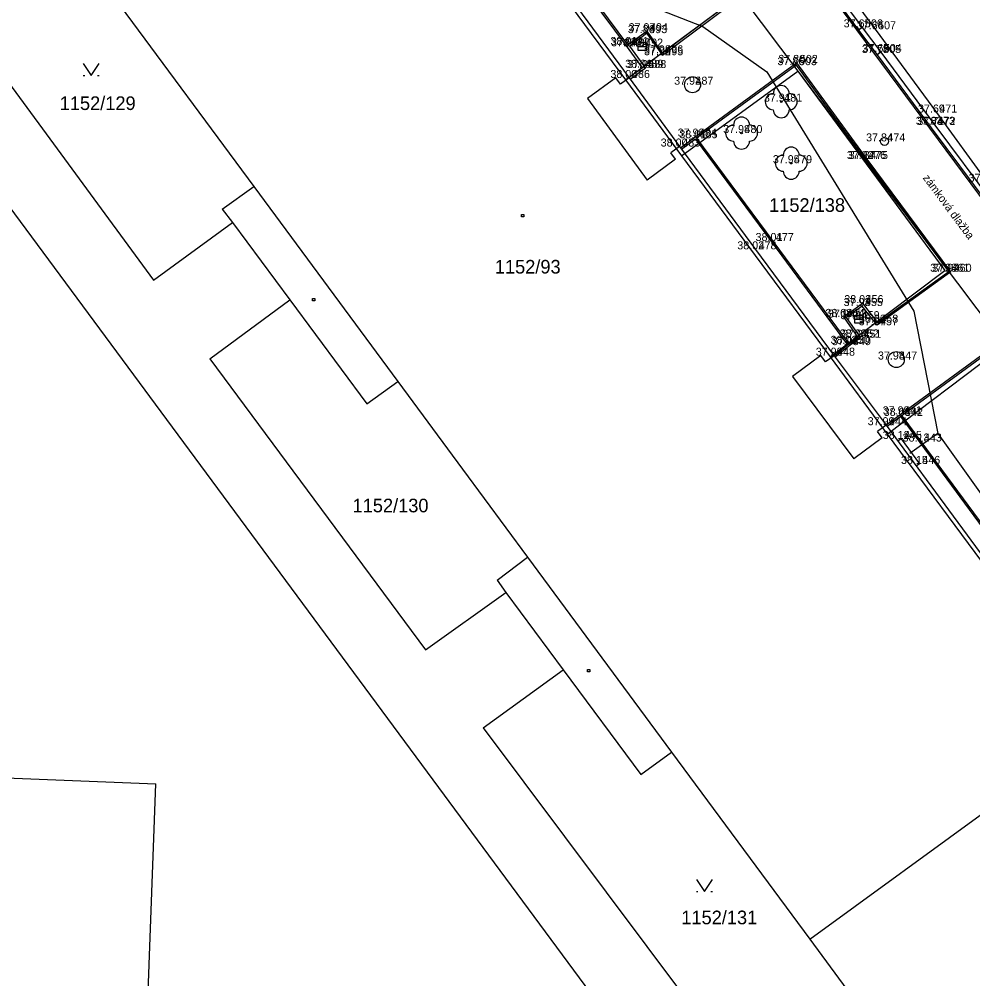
# Model space of a CAD drawing. Extents: x -609709 to -609357, y -1051535 to -1051131.
# Drawn here: x -609585.14 to -609555.38, y -1051361.09 to -1051331.13 of the extents above; entities that cross this region are included whole.
import ezdxf

# ---------------------------------------------------------------- set-up
doc = ezdxf.new("R2010")
doc.units = 0
for name, color, linetype in [('Vrstva 1', 7, 'Continuous'), ('Vrstva 10', 7, 'Continuous'), ('Vrstva 12', 7, 'Continuous'), ('Vrstva 2', 7, 'Continuous'), ('Vrstva 3', 7, 'Continuous'), ('Vrstva 4', 7, 'Continuous'), ('Vrstva 5', 7, 'Continuous'), ('Vrstva 7', 7, 'Continuous'), ('Vrstva 9', 7, 'Continuous')]:
    doc.layers.add(name, color=color, linetype=linetype)

msp = doc.modelspace()

# ---------------------------------------------------------------- linework, layer by layer
at = {"layer": 'Vrstva 1'}
for p, q in [((-609565.55, -1051331.51), (-609565.55, -1051331.51)), ((-609558.84, -1051331.39), (-609558.84, -1051331.39)), ((-609558.43, -1051331.45), (-609558.43, -1051331.45)), ((-609565.57, -1051331.57), (-609565.57, -1051331.57)), ((-609566.15, -1051331.94), (-609566.15, -1051331.94)), ((-609566.1, -1051331.98), (-609566.1, -1051331.98)), ((-609565.7, -1051331.99), (-609565.7, -1051331.99)), ((-609565.07, -1051332.2), (-609565.07, -1051332.2)), ((-609565.07, -1051332.26), (-609565.07, -1051332.26)), ((-609558.27, -1051332.19), (-609558.27, -1051332.19)), ((-609558.25, -1051332.16), (-609558.25, -1051332.16)), ((-609565.69, -1051332.65), (-609565.69, -1051332.65)), ((-609565.6, -1051332.66), (-609565.6, -1051332.66)), ((-609560.9, -1051332.57), (-609560.9, -1051332.57)), ((-609560.87, -1051332.5), (-609560.87, -1051332.5)), ((-609566.11, -1051332.97), (-609566.11, -1051332.97)), ((-609564.13, -1051333.18), (-609564.13, -1051333.18)), ((-609561.36, -1051333.71), (-609561.36, -1051333.71)), ((-609556.52, -1051334.05), (-609556.52, -1051334.05)), ((-609556.59, -1051334.43), (-609556.59, -1051334.43)), ((-609556.57, -1051334.44), (-609556.57, -1051334.44)), ((-609564.02, -1051334.8), (-609564.02, -1051334.8)), ((-609562.6, -1051334.69), (-609562.6, -1051334.69)), ((-609564.54, -1051335.11), (-609564.54, -1051335.11)), ((-609564, -1051334.85), (-609564, -1051334.85)), ((-609558.14, -1051334.95), (-609558.14, -1051334.95)), ((-609561.05, -1051335.63), (-609561.05, -1051335.63)), ((-609558.74, -1051335.5), (-609558.74, -1051335.5)), ((-609558.68, -1051335.5), (-609558.68, -1051335.5)), ((-609561.62, -1051338.06), (-609561.62, -1051338.06)), ((-609562.16, -1051338.32), (-609562.16, -1051338.32)), ((-609556.14, -1051339.02), (-609556.14, -1051339.02)), ((-609556.07, -1051339.02), (-609556.07, -1051339.02)), ((-609558.84, -1051340.09), (-609558.84, -1051340.09)), ((-609558.82, -1051340), (-609558.82, -1051340)), ((-609559.41, -1051340.43), (-609559.41, -1051340.43)), ((-609559.33, -1051340.45), (-609559.33, -1051340.45)), ((-609558.94, -1051340.5), (-609558.94, -1051340.5)), ((-609558.37, -1051340.69), (-609558.37, -1051340.69)), ((-609558.36, -1051340.61), (-609558.36, -1051340.61)), ((-609558.96, -1051341.07), (-609558.96, -1051341.07)), ((-609558.89, -1051341.08), (-609558.89, -1051341.08)), ((-609559.25, -1051341.27), (-609559.25, -1051341.27)), ((-609559.21, -1051341.31), (-609559.21, -1051341.31)), ((-609559.71, -1051341.64), (-609559.71, -1051341.64)), ((-609557.77, -1051341.76), (-609557.77, -1051341.76)), ((-609557.62, -1051343.47), (-609557.62, -1051343.47)), ((-609558.09, -1051343.81), (-609558.09, -1051343.81)), ((-609557.59, -1051343.52), (-609557.59, -1051343.52)), ((-609557.62, -1051344.24), (-609557.62, -1051344.24)), ((-609557, -1051344.32), (-609557, -1051344.32)), ((-609557.05, -1051345.02), (-609557.05, -1051345.02))]:
    msp.add_line(p, q, dxfattribs=at)
at = {"layer": 'Vrstva 10'}
for p, q in [((-609581.79, -1051300.71), (-609506.66, -1051402.14)), ((-609595.06, -1051324), (-609556.61, -1051376.01)), ((-609572.88, -1051324.02), (-609566.22, -1051333.03)), ((-609589.8, -1051327.23), (-609580.95, -1051339.28)), ((-609566.22, -1051333.03), (-609562.6, -1051330.34)), ((-609581.99, -1051330.72), (-609577.82, -1051336.36)), ((-609583.15, -1051332.515), (-609582.9, -1051332.89)), ((-609582.9, -1051332.89), (-609582.65, -1051332.515)), ((-609583.15, -1051332.89), (-609583.1, -1051332.89)), ((-609582.7, -1051332.89), (-609582.65, -1051332.89)), ((-609564.47, -1051335.4), (-609560.84, -1051332.76)), ((-609560.84, -1051332.76), (-609556.26, -1051338.98)), ((-609566.22, -1051333.03), (-609564.47, -1051335.4)), ((-609564.47, -1051335.4), (-609562.17, -1051338.51)), ((-609578.81, -1051337.07), (-609577.82, -1051336.36)), ((-609577.82, -1051336.36), (-609573.33, -1051342.45)), ((-609578.81, -1051337.07), (-609578.49, -1051337.48)), ((-609580.95, -1051339.28), (-609578.49, -1051337.48)), ((-609578.49, -1051337.48), (-609576.7, -1051339.9)), ((-609569.465, -1051337.235), (-609569.39, -1051337.235)), ((-609569.465, -1051337.31), (-609569.465, -1051337.235)), ((-609569.39, -1051337.31), (-609569.465, -1051337.31)), ((-609569.39, -1051337.235), (-609569.39, -1051337.31)), ((-609562.17, -1051338.51), (-609559.83, -1051341.68)), ((-609559.83, -1051341.68), (-609556.26, -1051338.98)), ((-609579.19, -1051341.74), (-609576.7, -1051339.9)), ((-609576.7, -1051339.9), (-609574.29, -1051343.14)), ((-609575.995, -1051339.855), (-609575.92, -1051339.855)), ((-609575.995, -1051339.93), (-609575.995, -1051339.855)), ((-609575.92, -1051339.855), (-609575.92, -1051339.93)), ((-609575.92, -1051339.93), (-609575.995, -1051339.93)), ((-609558.05, -1051344.09), (-609554.47, -1051341.38)), ((-609559.83, -1051341.68), (-609558.05, -1051344.09)), ((-609579.19, -1051341.74), (-609572.46, -1051350.82)), ((-609574.29, -1051343.14), (-609573.33, -1051342.45)), ((-609573.33, -1051342.45), (-609571.31, -1051345.18)), ((-609558.05, -1051344.09), (-609551.33, -1051353.19)), ((-609571.31, -1051345.18), (-609569.28, -1051347.93)), ((-609570.23, -1051348.65), (-609569.28, -1051347.93)), ((-609569.28, -1051347.93), (-609564.79, -1051354.02)), ((-609570.23, -1051348.65), (-609569.96, -1051349.03)), ((-609572.46, -1051350.82), (-609569.96, -1051349.03)), ((-609569.96, -1051349.03), (-609568.17, -1051351.45)), ((-609570.66, -1051353.26), (-609568.17, -1051351.45)), ((-609568.17, -1051351.45), (-609565.74, -1051354.72)), ((-609567.405, -1051351.435), (-609567.33, -1051351.435)), ((-609567.405, -1051351.51), (-609567.405, -1051351.435)), ((-609567.33, -1051351.51), (-609567.405, -1051351.51)), ((-609567.33, -1051351.435), (-609567.33, -1051351.51)), ((-609570.66, -1051353.26), (-609559.22, -1051368.54)), ((-609560.47, -1051359.86), (-609551.33, -1051353.19)), ((-609565.74, -1051354.72), (-609564.79, -1051354.02)), ((-609564.79, -1051354.02), (-609560.47, -1051359.86)), ((-609592.98, -1051354.53), (-609580.88, -1051355.01)), ((-609581.73, -1051378.07), (-609580.88, -1051355.01)), ((-609564.01, -1051357.995), (-609563.76, -1051358.37)), ((-609563.76, -1051358.37), (-609563.51, -1051357.995)), ((-609564.01, -1051358.37), (-609563.96, -1051358.37)), ((-609563.56, -1051358.37), (-609563.51, -1051358.37)), ((-609560.47, -1051359.86), (-609556.16, -1051365.7))]:
    msp.add_line(p, q, dxfattribs=at)
at = {"layer": 'Vrstva 12'}
for points in [[(-609615.546, -1051325.052), (-609614.108, -1051326.974), (-609589.099, -1051308.266), (-609582.815, -1051303.565), (-609514.844, -1051393.856), (-609499.807, -1051382.785), (-609467.693, -1051377.467)], [(-609567.26, -1051329.65), (-609566.61, -1051330.26), (-609563.81, -1051331.36), (-609561.81, -1051332.78), (-609557.22, -1051340.25), (-609556.47, -1051344.07), (-609557.345, -1051344.694)], [(-609556.47, -1051344.07), (-609551.22, -1051351.43), (-609546.41, -1051357.3), (-609545.59, -1051359.13), (-609546.284, -1051359.683)]]:
    msp.add_lwpolyline(points, dxfattribs=at)
at = {"layer": 'Vrstva 4'}
msp.add_line((-609566.19, -1051331.97), (-609569.24, -1051327.85), dxfattribs=at)
for points in [[(-609581.29, -1051300.49), (-609578.2, -1051304.72), (-609575.96, -1051307.74), (-609573.15, -1051311.54), (-609570.93, -1051314.56), (-609567.02, -1051319.88), (-609560.65, -1051328.46), (-609558.43, -1051331.45), (-609556.52, -1051334.05), (-609554.94, -1051336.21), (-609551.65, -1051340.58), (-609547.88, -1051345.71), (-609545.37, -1051349.12), (-609543.12, -1051352.14), (-609541.57, -1051354.24), (-609540.598, -1051355.492)], [(-609578.94, -1051314.61), (-609575.88, -1051312.34), (-609572.62, -1051316.75), (-609569.1, -1051321.53), (-609566.09, -1051325.58), (-609562.57, -1051330.32), (-609565.07, -1051332.2), (-609565.55, -1051331.51), (-609566.15, -1051331.94)], [(-609566.15, -1051331.94), (-609569.2, -1051327.82), (-609572.12, -1051323.85), (-609575.24, -1051319.63), (-609578.94, -1051314.61)], [(-609560.734, -1051329.062), (-609558.952, -1051331.474), (-609558.362, -1051332.244), (-609556.683, -1051334.523), (-609554.883, -1051336.942), (-609554.333, -1051337.712), (-609552.562, -1051340.114), (-609551.952, -1051340.904), (-609548.222, -1051345.943), (-609545.692, -1051349.353), (-609543.904, -1051351.772), (-609543.324, -1051352.602), (-609541.542, -1051355.005), (-609540.951, -1051355.766)], [(-609560.62, -1051328.98), (-609558.84, -1051331.39), (-609558.25, -1051332.16), (-609556.57, -1051334.44), (-609554.77, -1051336.86), (-609554.22, -1051337.63), (-609552.45, -1051340.03), (-609551.84, -1051340.82), (-609548.11, -1051345.86), (-609545.58, -1051349.27), (-609543.79, -1051351.69), (-609543.21, -1051352.52), (-609541.43, -1051354.92), (-609540.84, -1051355.68)], [(-609566.1, -1051331.98), (-609565.57, -1051331.57), (-609565.07, -1051332.26), (-609562.5, -1051330.33)], [(-609558.84, -1051331.39), (-609558.952, -1051331.474)], [(-609565.69, -1051332.65), (-609566.19, -1051331.97)], [(-609566.1, -1051331.98), (-609565.6, -1051332.66)], [(-609558.25, -1051332.16), (-609558.362, -1051332.244)], [(-609565.69, -1051332.65), (-609566.115, -1051332.963)], [(-609565.6, -1051332.66), (-609566.079, -1051333.013)], [(-609556.07, -1051339.02), (-609558.68, -1051335.5), (-609560.87, -1051332.5), (-609564.02, -1051334.8)], [(-609556.135, -1051339.016), (-609558.72, -1051335.53), (-609560.881, -1051332.57), (-609564.001, -1051334.848)], [(-609564.02, -1051334.8), (-609564.504, -1051335.159)], [(-609564.04, -1051334.88), (-609564.473, -1051335.201)], [(-609564.04, -1051334.88), (-609561.66, -1051338.09), (-609559.29, -1051341.3)], [(-609564.001, -1051334.848), (-609561.62, -1051338.06), (-609559.25, -1051341.27)], [(-609559.25, -1051341.27), (-609558.96, -1051341.07), (-609559.41, -1051340.43), (-609558.82, -1051340), (-609558.36, -1051340.61), (-609556.135, -1051339.016)], [(-609556.07, -1051339.02), (-609558.37, -1051340.69), (-609558.84, -1051340.09), (-609559.33, -1051340.45), (-609558.89, -1051341.08), (-609559.21, -1051341.31)], [(-609559.71, -1051341.64), (-609559.25, -1051341.27)], [(-609559.21, -1051341.31), (-609559.676, -1051341.685)], [(-609545.08, -1051353.89), (-609547.45, -1051350.69), (-609550.1, -1051347.09), (-609554.49, -1051341.18), (-609557.62, -1051343.47)], [(-609545.15, -1051353.879), (-609547.49, -1051350.72), (-609550.14, -1051347.12), (-609554.501, -1051341.25), (-609557.59, -1051343.51)], [(-609557.62, -1051343.47), (-609558.087, -1051343.814)], [(-609557.59, -1051343.51), (-609558.057, -1051343.854)], [(-609557.635, -1051343.543), (-609557.04, -1051344.35), (-609553.26, -1051349.48), (-609550.65, -1051353.02), (-609548.291, -1051356.189)], [(-609557.595, -1051343.514), (-609557, -1051344.32), (-609553.22, -1051349.45), (-609550.61, -1051352.99), (-609548.25, -1051356.16)]]:
    msp.add_lwpolyline(points, dxfattribs=at)
at = {"layer": 'Vrstva 5'}
for p, q in [((-609565.825, -1051331.99), (-609565.575, -1051331.99)), ((-609559.065, -1051340.5), (-609558.815, -1051340.5))]:
    msp.add_line(p, q, dxfattribs=at)
for points in [[(-609565.825, -1051331.865), (-609565.575, -1051331.865), (-609565.575, -1051332.115), (-609565.825, -1051332.115)], [(-609559.065, -1051340.375), (-609558.815, -1051340.375), (-609558.815, -1051340.625), (-609559.065, -1051340.625)]]:
    msp.add_lwpolyline(points, close=True, dxfattribs=at)
for centre, radius in [((-609564.13, -1051333.18), 0.25), ((-609558.14, -1051334.95), 0.125), ((-609557.77, -1051341.76), 0.25)]:
    msp.add_circle(centre, radius, dxfattribs=at)
at = {"layer": 'Vrstva 7'}
for centre in [(-609561.36, -1051333.71), (-609562.6, -1051334.69), (-609561.05, -1051335.63)]:
    msp.add_circle(centre, 0.025, dxfattribs=at)
for centre, start, end in [((-609561.36, -1051333.46), 0, 180), ((-609561.61, -1051333.71), 90, 270), ((-609561.11, -1051333.71), 270, 90), ((-609562.6, -1051334.44), 0, 180), ((-609561.36, -1051333.96), 180, 0), ((-609562.85, -1051334.69), 90, 270), ((-609562.35, -1051334.69), 270, 90), ((-609562.6, -1051334.94), 180, 0), ((-609561.3, -1051335.63), 90, 270), ((-609561.05, -1051335.38), 0, 180), ((-609560.8, -1051335.63), 270, 90), ((-609561.05, -1051335.88), 180, 0)]:
    msp.add_arc(centre, 0.25, start, end, dxfattribs=at)
at = {"layer": 'Vrstva 9'}
for points in [[(-609579.46, -1051314.88), (-609575.7, -1051319.98), (-609572.56, -1051324.24), (-609569.69, -1051328.11), (-609566.11, -1051332.97)], [(-609566.524, -1051332.964), (-609567.41, -1051333.616)], [(-609566.376, -1051333.166), (-609566.524, -1051332.964)], [(-609566.11, -1051332.97), (-609566.376, -1051333.166)], [(-609566.11, -1051332.97), (-609564.54, -1051335.11)], [(-609567.41, -1051333.616), (-609565.544, -1051336.159)], [(-609564.54, -1051335.11), (-609564.806, -1051335.306)], [(-609564.54, -1051335.11), (-609562.16, -1051338.32), (-609559.71, -1051341.64)], [(-609564.658, -1051335.507), (-609564.806, -1051335.306)], [(-609564.658, -1051335.507), (-609565.544, -1051336.159)], [(-609560.124, -1051341.634), (-609561.01, -1051342.286)], [(-609559.976, -1051341.836), (-609560.124, -1051341.634)], [(-609559.71, -1051341.64), (-609559.976, -1051341.836)], [(-609559.71, -1051341.64), (-609558.09, -1051343.81)], [(-609561.01, -1051342.286), (-609559.094, -1051344.859)], [(-609558.09, -1051343.81), (-609558.356, -1051344.006)], [(-609558.09, -1051343.81), (-609553.61, -1051349.89), (-609551.1, -1051353.3), (-609548.71, -1051356.55)], [(-609558.208, -1051344.207), (-609558.356, -1051344.006)], [(-609558.208, -1051344.207), (-609559.094, -1051344.859)], [(-609557.62, -1051344.24), (-609557.719, -1051344.313)], [(-609557.62, -1051344.24), (-609557.05, -1051345.02), (-609557.146, -1051345.091)]]:
    msp.add_lwpolyline(points, dxfattribs=at)

# ---------------------------------------------------------------- texts
at = {"layer": 'Vrstva 10'}
for s, p in [('1152/129', (-609583.88, -1051333.97)), ('1152/138', (-609561.74, -1051337.15)), ('1152/93', (-609570.3, -1051339.075)), ('1152/130', (-609574.74, -1051346.53)), ('1152/131', (-609564.48, -1051359.39))]:
    msp.add_text(s, height=0.425, dxfattribs=at).set_placement(p)
at = {"layer": 'Vrstva 2'}
for s, p in [(' 506', (-609558.84, -1051331.39)), (' 507', (-609558.43, -1051331.45)), (' 493', (-609565.57, -1051331.57)), (' 494', (-609565.55, -1051331.51)), (' 491', (-609566.15, -1051331.94)), (' 490', (-609566.1, -1051331.98)), (' 492', (-609565.7, -1051331.99)), (' 496', (-609565.07, -1051332.2)), (' 495', (-609565.07, -1051332.26)), (' 505', (-609558.27, -1051332.19)), (' 504', (-609558.25, -1051332.16)), (' 489', (-609565.69, -1051332.65)), (' 488', (-609565.6, -1051332.66)), (' 503', (-609560.9, -1051332.57)), (' 502', (-609560.87, -1051332.5)), (' 486', (-609566.11, -1051332.97)), (' 487', (-609564.13, -1051333.18)), (' 481', (-609561.36, -1051333.71)), (' 471', (-609556.52, -1051334.05)), (' 473', (-609556.59, -1051334.43)), (' 472', (-609556.57, -1051334.44)), (' 480', (-609562.6, -1051334.69)), (' 484', (-609564.02, -1051334.8)), (' 485', (-609564, -1051334.85)), (' 474', (-609558.14, -1051334.95)), (' 483', (-609564.54, -1051335.11)), (' 479', (-609561.05, -1051335.63)), (' 476', (-609558.74, -1051335.5)), (' 475', (-609558.68, -1051335.5)), (' 477', (-609561.62, -1051338.06)), (' 478', (-609562.16, -1051338.32)), (' 461', (-609556.14, -1051339.02)), (' 460', (-609556.07, -1051339.02)), (' 455', (-609558.84, -1051340.09)), (' 456', (-609558.82, -1051340)), (' 454', (-609559.41, -1051340.43)), (' 453', (-609559.33, -1051340.45)), (' 459', (-609558.94, -1051340.5)), (' 457', (-609558.37, -1051340.69)), (' 458', (-609558.36, -1051340.61)), (' 450', (-609559.25, -1051341.27)), (' 449', (-609559.21, -1051341.31)), (' 452', (-609558.96, -1051341.07)), (' 451', (-609558.89, -1051341.08)), (' 448', (-609559.71, -1051341.64)), (' 447', (-609557.77, -1051341.76)), (' 441', (-609557.62, -1051343.47)), (' 442', (-609557.59, -1051343.52)), (' 444', (-609558.09, -1051343.81)), (' 445', (-609557.62, -1051344.24)), (' 443', (-609557, -1051344.32)), (' 446', (-609557.05, -1051345.02))]:
    msp.add_text(s, height=0.25, dxfattribs=at).set_placement(p)
at = {"layer": 'Vrstva 3'}
for s, p in [('37.65', (-609559.413, -1051331.39)), ('37.64', (-609559.003, -1051331.45)), ('37.86', (-609566.149, -1051331.57)), ('37.97', (-609566.123, -1051331.51)), ('38.01', (-609566.692, -1051331.94)), ('37.87', (-609566.673, -1051331.98)), ('37.87', (-609566.273, -1051331.99)), ('37.98', (-609565.643, -1051332.2)), ('37.92', (-609565.643, -1051332.26)), ('37.78', (-609558.843, -1051332.19)), ('37.67', (-609558.823, -1051332.16)), ('38.01', (-609566.232, -1051332.65)), ('37.93', (-609566.173, -1051332.66)), ('37.86', (-609561.479, -1051332.57)), ('37.80', (-609561.453, -1051332.5)), ('38.00', (-609566.693, -1051332.97)), ('37.92', (-609564.703, -1051333.18)), ('37.91', (-609561.902, -1051333.71)), ('37.69', (-609557.093, -1051334.05)), ('37.83', (-609557.163, -1051334.43)), ('37.71', (-609557.112, -1051334.44)), ('37.98', (-609563.173, -1051334.69)), ('37.98', (-609564.593, -1051334.8)), ('38.01', (-609564.542, -1051334.85)), ('37.84', (-609558.713, -1051334.95)), ('38.00', (-609565.123, -1051335.11)), ('37.95', (-609561.623, -1051335.63)), ('37.92', (-609559.313, -1051335.5)), ('37.87', (-609559.253, -1051335.5)), ('37.74', (-609555.513, -1051336.21)), ('38.01', (-609562.162, -1051338.06)), ('38.02', (-609562.733, -1051338.32)), ('37.98', (-609556.713, -1051339.02)), ('37.92', (-609556.643, -1051339.02)), ('37.93', (-609559.413, -1051340.09)), ('38.03', (-609559.393, -1051340)), ('38.03', (-609559.983, -1051340.43)), ('37.94', (-609559.903, -1051340.45)), ('37.94', (-609559.513, -1051340.5)), ('37.97', (-609558.943, -1051340.69)), ('38.02', (-609558.933, -1051340.61)), ('38.02', (-609559.823, -1051341.27)), ('37.98', (-609559.783, -1051341.31)), ('38.03', (-609559.533, -1051341.07)), ('37.97', (-609559.463, -1051341.08)), ('37.99', (-609560.283, -1051341.64)), ('37.98', (-609558.343, -1051341.76)), ('37.99', (-609558.193, -1051343.47)), ('38.03', (-609558.163, -1051343.52)), ('37.99', (-609558.663, -1051343.81)), ('38.12', (-609558.193, -1051344.24)), ('38.13', (-609557.573, -1051344.32)), ('38.15', (-609557.623, -1051345.02))]:
    msp.add_text(s, height=0.25, dxfattribs=at).set_placement(p)
at = {"layer": 'Vrstva 4'}
msp.add_text('zámková dlažba', height=0.25, rotation=306.5561, dxfattribs=at).set_placement((-609556.955, -1051336.092))

doc.saveas('drawing.dxf')
